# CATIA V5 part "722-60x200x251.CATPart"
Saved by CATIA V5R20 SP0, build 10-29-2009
Part number: 722-60x200x251
Definition: NONE
Nomenclature: 722-60x200x251
Source: Unknown
Description: 722-60x200x251
Bounding box of the stored display mesh (mm): x -30 to 30, y -30 to 30, z -182 to 69
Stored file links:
  C:\Users\Utente\Desktop\IO LAVORO\3D X SITO CF\X SITO\722\722-60x200x251.CATPart
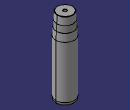
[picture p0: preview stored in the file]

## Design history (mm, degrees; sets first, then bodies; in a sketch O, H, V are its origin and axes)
Body1 "722-60x200x251" (main body)
  Solid1: solid without history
